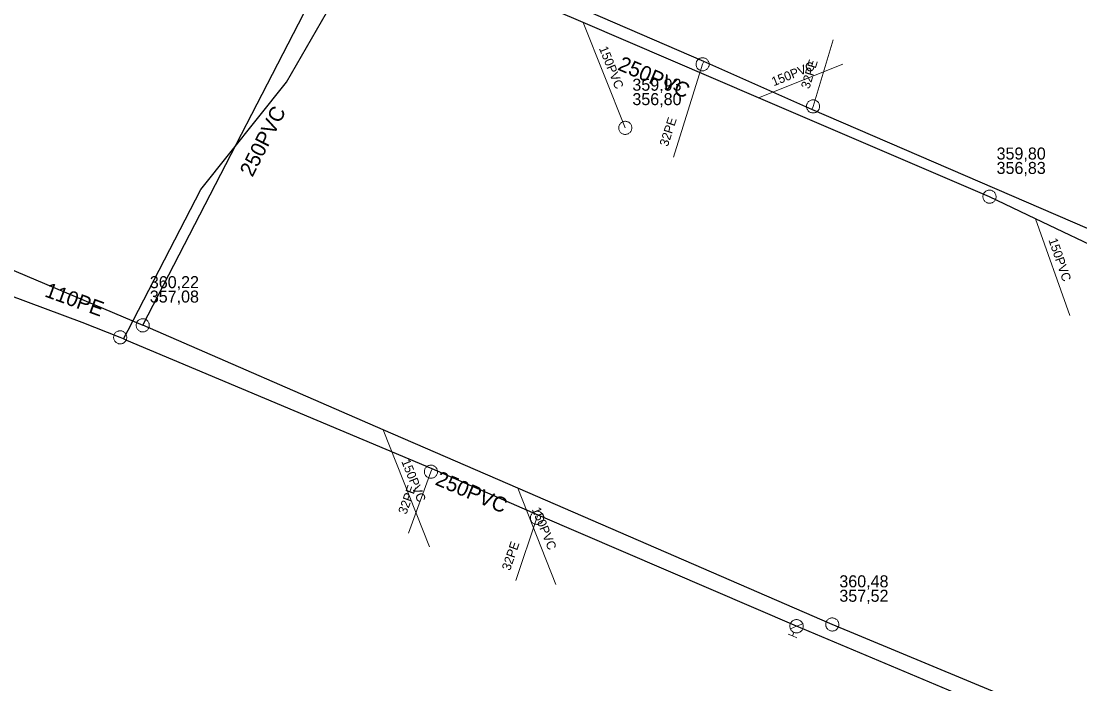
# Model space of a CAD drawing. Extents: x -741806 to -738704, y -1059275 to -1055387.
# Drawn here: x -740647.7 to -740577.2, y -1058217.7 to -1058173.6 of the extents above; entities that cross this region are included whole.
import ezdxf

# ---------------------------------------------------------------- set-up
doc = ezdxf.new("R2010")
doc.units = 0
doc.header["$LTSCALE"] = 0.4
for name, color, linetype, lineweight in [('2', 7, 'Continuous', 25), ('21', 7, 'Continuous', 13), ('3', 7, 'Continuous', 13), ('50', 7, 'Continuous', 13), ('51', 7, 'Continuous', 13), ('52', 7, 'Continuous', 25), ('56', 7, 'Continuous', 13), ('6', 7, 'Continuous', 13)]:
    doc.layers.add(name, color=color, linetype=linetype, lineweight=lineweight)
for name, color, linetype in [('5', 7, 'Continuous'), ('53', 7, 'Continuous'), ('54', 7, 'Continuous'), ('55', 7, 'Continuous')]:
    doc.layers.add(name, color=color, linetype=linetype)

msp = doc.modelspace()

# ---------------------------------------------------------------- linework, layer by layer
at = {"layer": '2'}
for points in [[(-740583.26, -1058185.25), (-740598.636, -1058178.666), (-740610.313, -1058173.665), (-740625.809, -1058167.03), (-740606.009, -1058125.064), (-740592.5, -1058086.389)], [(-740593.73, -1058213.72), (-740614.653, -1058204.646), (-740623.623, -1058200.756), (-740639.64, -1058193.81), (-740625.809, -1058167.03)], [(-740660.07, -1058185.139), (-740658.399, -1058185.85), (-740639.64, -1058193.81)], [(-740538.76, -1058206.54), (-740547.691, -1058202.267), (-740571.346, -1058190.95), (-740575.151, -1058189.129), (-740580.188, -1058186.719), (-740583.26, -1058185.25)], [(-740548.32, -1058232.629), (-740563.6, -1058226.267), (-740576.074, -1058221.071), (-740593.73, -1058213.72)]]:
    msp.add_lwpolyline(points, dxfattribs=at)
at = {"layer": '21'}
for points in [[(-740595.099, -1058179.439), (-740595.009, -1058179.237), (-740593.67, -1058174.82)], [(-740602.27, -1058176.253), (-740602.363, -1058176.438), (-740604.289, -1058182.62)], [(-740620.362, -1058203.362), (-740620.449, -1058203.55), (-740621.94, -1058207.639)], [(-740613.302, -1058206.436), (-740613.39, -1058206.62), (-740614.8, -1058210.79)]]:
    msp.add_lwpolyline(points, dxfattribs=at)
at = {"layer": '3'}
for points in [[(-740607.672, -1058180.262), (-740607.712, -1058180.281), (-740607.752, -1058180.304), (-740607.789, -1058180.332), (-740607.822, -1058180.363), (-740607.852, -1058180.397), (-740607.879, -1058180.435), (-740607.901, -1058180.475), (-740607.92, -1058180.517), (-740607.932, -1058180.561), (-740607.941, -1058180.605), (-740607.946, -1058180.651), (-740607.945, -1058180.698), (-740607.939, -1058180.743), (-740607.93, -1058180.787), (-740607.915, -1058180.831), (-740607.896, -1058180.873), (-740607.872, -1058180.911), (-740607.845, -1058180.948), (-740607.813, -1058180.982), (-740607.779, -1058181.012), (-740607.741, -1058181.038), (-740607.702, -1058181.06), (-740607.659, -1058181.079), (-740607.616, -1058181.092), (-740607.571, -1058181.101), (-740607.525, -1058181.105), (-740607.48, -1058181.105), (-740607.434, -1058181.099), (-740607.389, -1058181.089), (-740607.346, -1058181.074), (-740607.305, -1058181.055), (-740607.265, -1058181.032), (-740607.228, -1058181.004), (-740607.195, -1058180.972), (-740607.165, -1058180.939), (-740607.138, -1058180.901), (-740607.116, -1058180.861), (-740607.098, -1058180.818), (-740607.085, -1058180.775), (-740607.076, -1058180.731), (-740607.072, -1058180.685), (-740607.072, -1058180.639), (-740607.077, -1058180.593), (-740607.087, -1058180.549), (-740607.102, -1058180.506), (-740607.121, -1058180.464), (-740607.145, -1058180.424), (-740607.172, -1058180.388), (-740607.204, -1058180.354), (-740607.239, -1058180.324), (-740607.276, -1058180.298), (-740607.315, -1058180.275), (-740607.358, -1058180.258), (-740607.401, -1058180.244), (-740607.447, -1058180.235), (-740607.492, -1058180.231), (-740607.537, -1058180.232), (-740607.584, -1058180.237), (-740607.628, -1058180.247), (-740607.671, -1058180.261)], [(-740583.654, -1058185.06), (-740583.671, -1058185.102), (-740583.684, -1058185.146), (-740583.693, -1058185.191), (-740583.697, -1058185.236), (-740583.695, -1058185.282), (-740583.69, -1058185.328), (-740583.678, -1058185.372), (-740583.664, -1058185.416), (-740583.643, -1058185.457), (-740583.62, -1058185.496), (-740583.592, -1058185.532), (-740583.561, -1058185.566), (-740583.526, -1058185.595), (-740583.488, -1058185.622), (-740583.448, -1058185.643), (-740583.405, -1058185.661), (-740583.361, -1058185.674), (-740583.317, -1058185.683), (-740583.271, -1058185.686), (-740583.225, -1058185.685), (-740583.18, -1058185.678), (-740583.136, -1058185.668), (-740583.092, -1058185.653), (-740583.051, -1058185.634), (-740583.011, -1058185.609), (-740582.976, -1058185.581), (-740582.942, -1058185.55), (-740582.912, -1058185.515), (-740582.886, -1058185.477), (-740582.865, -1058185.437), (-740582.847, -1058185.395), (-740582.834, -1058185.352), (-740582.825, -1058185.306), (-740582.822, -1058185.26), (-740582.823, -1058185.215), (-740582.829, -1058185.169), (-740582.84, -1058185.125), (-740582.855, -1058185.081), (-740582.875, -1058185.041), (-740582.898, -1058185.002), (-740582.926, -1058184.965), (-740582.958, -1058184.931), (-740582.992, -1058184.901), (-740583.03, -1058184.876), (-740583.07, -1058184.854), (-740583.113, -1058184.836), (-740583.156, -1058184.823), (-740583.201, -1058184.815), (-740583.247, -1058184.811), (-740583.293, -1058184.813), (-740583.338, -1058184.819), (-740583.383, -1058184.829), (-740583.426, -1058184.844), (-740583.467, -1058184.864), (-740583.507, -1058184.888), (-740583.543, -1058184.916), (-740583.576, -1058184.947), (-740583.606, -1058184.982), (-740583.632, -1058185.02), (-740583.654, -1058185.059)], [(-740639.438, -1058193.421), (-740639.479, -1058193.403), (-740639.523, -1058193.388), (-740639.568, -1058193.378), (-740639.613, -1058193.373), (-740639.659, -1058193.373), (-740639.705, -1058193.377), (-740639.749, -1058193.387), (-740639.793, -1058193.4), (-740639.835, -1058193.419), (-740639.874, -1058193.442), (-740639.912, -1058193.468), (-740639.947, -1058193.499), (-740639.977, -1058193.533), (-740640.004, -1058193.569), (-740640.027, -1058193.609), (-740640.047, -1058193.651), (-740640.06, -1058193.695), (-740640.071, -1058193.739), (-740640.075, -1058193.785), (-740640.075, -1058193.831), (-740640.071, -1058193.876), (-740640.062, -1058193.92), (-740640.048, -1058193.965), (-740640.03, -1058194.006), (-740640.007, -1058194.046), (-740639.979, -1058194.083), (-740639.95, -1058194.117), (-740639.915, -1058194.149), (-740639.879, -1058194.176), (-740639.839, -1058194.198), (-740639.798, -1058194.217), (-740639.755, -1058194.232), (-740639.709, -1058194.242), (-740639.663, -1058194.246), (-740639.618, -1058194.247), (-740639.572, -1058194.243), (-740639.528, -1058194.233), (-740639.483, -1058194.219), (-740639.442, -1058194.201), (-740639.403, -1058194.178), (-740639.365, -1058194.151), (-740639.33, -1058194.121), (-740639.3, -1058194.087), (-740639.273, -1058194.051), (-740639.25, -1058194.011), (-740639.231, -1058193.969), (-740639.216, -1058193.926), (-740639.207, -1058193.881), (-740639.202, -1058193.835), (-740639.202, -1058193.789), (-740639.207, -1058193.744), (-740639.215, -1058193.699), (-740639.23, -1058193.655), (-740639.247, -1058193.614), (-740639.271, -1058193.573), (-740639.297, -1058193.536), (-740639.327, -1058193.503), (-740639.362, -1058193.471), (-740639.399, -1058193.444), (-740639.437, -1058193.421)], [(-740594.134, -1058213.551), (-740594.148, -1058213.593), (-740594.159, -1058213.638), (-740594.165, -1058213.684), (-740594.167, -1058213.729), (-740594.163, -1058213.775), (-740594.155, -1058213.82), (-740594.142, -1058213.864), (-740594.125, -1058213.906), (-740594.102, -1058213.946), (-740594.077, -1058213.984), (-740594.047, -1058214.019), (-740594.014, -1058214.051), (-740593.977, -1058214.078), (-740593.939, -1058214.103), (-740593.897, -1058214.122), (-740593.854, -1058214.138), (-740593.809, -1058214.148), (-740593.765, -1058214.155), (-740593.718, -1058214.156), (-740593.672, -1058214.152), (-740593.628, -1058214.144), (-740593.585, -1058214.131), (-740593.542, -1058214.114), (-740593.501, -1058214.092), (-740593.463, -1058214.066), (-740593.429, -1058214.036), (-740593.397, -1058214.004), (-740593.369, -1058213.967), (-740593.345, -1058213.928), (-740593.326, -1058213.886), (-740593.31, -1058213.844), (-740593.299, -1058213.8), (-740593.293, -1058213.753), (-740593.292, -1058213.707), (-740593.295, -1058213.663), (-740593.303, -1058213.617), (-740593.317, -1058213.573), (-740593.334, -1058213.53), (-740593.356, -1058213.491), (-740593.381, -1058213.453), (-740593.411, -1058213.418), (-740593.444, -1058213.386), (-740593.48, -1058213.358), (-740593.519, -1058213.334), (-740593.561, -1058213.315), (-740593.604, -1058213.299), (-740593.648, -1058213.288), (-740593.694, -1058213.282), (-740593.74, -1058213.281), (-740593.786, -1058213.285), (-740593.83, -1058213.293), (-740593.874, -1058213.305), (-740593.917, -1058213.324), (-740593.957, -1058213.345), (-740593.995, -1058213.371), (-740594.03, -1058213.401), (-740594.061, -1058213.434), (-740594.089, -1058213.471), (-740594.113, -1058213.509), (-740594.133, -1058213.55)]]:
    msp.add_lwpolyline(points, dxfattribs=at)
at = {"layer": '50'}
for p, q in [((-740596.107, -1058213.835), (-740596.518, -1058214.001)), ((-740596.279, -1058214.248), (-740596.376, -1058214.479)), ((-740596.107, -1058213.835), (-740595.692, -1058213.666)), ((-740596.659, -1058214.36), (-740596.376, -1058214.479)), ((-740596.092, -1058214.599), (-740596.376, -1058214.479))]:
    msp.add_line(p, q, dxfattribs=at)
msp.add_lwpolyline([(-740596.515, -1058213.66), (-740596.531, -1058213.706), (-740596.544, -1058213.75), (-740596.55, -1058213.798), (-740596.551, -1058213.844), (-740596.549, -1058213.888), (-740596.54, -1058213.937), (-740596.527, -1058213.98), (-740596.51, -1058214.025), (-740596.489, -1058214.066), (-740596.461, -1058214.104), (-740596.432, -1058214.14), (-740596.4, -1058214.174), (-740596.361, -1058214.201), (-740596.322, -1058214.226), (-740596.281, -1058214.247), (-740596.237, -1058214.262), (-740596.194, -1058214.275), (-740596.146, -1058214.281), (-740596.099, -1058214.282), (-740596.051, -1058214.279), (-740596.007, -1058214.271), (-740595.961, -1058214.259), (-740595.918, -1058214.241), (-740595.878, -1058214.22), (-740595.838, -1058214.194), (-740595.801, -1058214.164), (-740595.77, -1058214.131), (-740595.739, -1058214.094), (-740595.717, -1058214.053), (-740595.693, -1058214.013), (-740595.678, -1058213.968), (-740595.667, -1058213.922), (-740595.661, -1058213.879), (-740595.658, -1058213.83), (-740595.662, -1058213.784), (-740595.669, -1058213.737), (-740595.683, -1058213.694), (-740595.699, -1058213.649), (-740595.722, -1058213.607), (-740595.748, -1058213.57), (-740595.779, -1058213.533), (-740595.812, -1058213.501), (-740595.847, -1058213.472), (-740595.889, -1058213.445), (-740595.93, -1058213.425), (-740595.973, -1058213.41), (-740596.019, -1058213.399), (-740596.066, -1058213.392), (-740596.111, -1058213.39), (-740596.16, -1058213.393), (-740596.204, -1058213.401), (-740596.251, -1058213.414), (-740596.293, -1058213.431), (-740596.334, -1058213.451), (-740596.372, -1058213.48), (-740596.409, -1058213.508), (-740596.442, -1058213.541), (-740596.469, -1058213.579), (-740596.494, -1058213.618)], close=True, dxfattribs=at)
at = {"layer": '51'}
for points in [[(-740601.926, -1058176.438), (-740601.928, -1058176.393), (-740601.935, -1058176.348), (-740601.947, -1058176.303), (-740601.963, -1058176.261), (-740601.984, -1058176.22), (-740602.009, -1058176.181), (-740602.038, -1058176.146), (-740602.07, -1058176.113), (-740602.106, -1058176.085), (-740602.144, -1058176.06), (-740602.185, -1058176.039), (-740602.228, -1058176.022), (-740602.272, -1058176.01), (-740602.317, -1058176.003), (-740602.363, -1058176.001), (-740602.409, -1058176.003), (-740602.454, -1058176.01), (-740602.498, -1058176.022), (-740602.541, -1058176.039), (-740602.582, -1058176.06), (-740602.62, -1058176.085), (-740602.656, -1058176.113), (-740602.688, -1058176.146), (-740602.717, -1058176.181), (-740602.742, -1058176.22), (-740602.763, -1058176.261), (-740602.779, -1058176.303), (-740602.791, -1058176.348), (-740602.798, -1058176.393), (-740602.801, -1058176.439), (-740602.798, -1058176.484), (-740602.791, -1058176.529), (-740602.779, -1058176.574), (-740602.763, -1058176.616), (-740602.742, -1058176.657), (-740602.717, -1058176.696), (-740602.688, -1058176.731), (-740602.656, -1058176.764), (-740602.62, -1058176.792), (-740602.582, -1058176.817), (-740602.541, -1058176.838), (-740602.498, -1058176.855), (-740602.454, -1058176.866), (-740602.409, -1058176.874), (-740602.363, -1058176.876), (-740602.317, -1058176.874), (-740602.272, -1058176.866), (-740602.228, -1058176.855), (-740602.185, -1058176.838), (-740602.144, -1058176.817), (-740602.106, -1058176.792), (-740602.07, -1058176.764), (-740602.038, -1058176.731), (-740602.009, -1058176.696), (-740601.984, -1058176.657), (-740601.963, -1058176.616), (-740601.947, -1058176.574), (-740601.935, -1058176.529), (-740601.928, -1058176.484), (-740601.926, -1058176.439)], [(-740594.571, -1058179.237), (-740594.573, -1058179.192), (-740594.581, -1058179.147), (-740594.593, -1058179.102), (-740594.608, -1058179.06), (-740594.63, -1058179.019), (-740594.654, -1058178.98), (-740594.684, -1058178.945), (-740594.716, -1058178.912), (-740594.752, -1058178.884), (-740594.789, -1058178.859), (-740594.831, -1058178.838), (-740594.874, -1058178.821), (-740594.918, -1058178.809), (-740594.963, -1058178.802), (-740595.009, -1058178.8), (-740595.054, -1058178.802), (-740595.1, -1058178.809), (-740595.144, -1058178.821), (-740595.186, -1058178.838), (-740595.228, -1058178.859), (-740595.266, -1058178.884), (-740595.301, -1058178.912), (-740595.333, -1058178.945), (-740595.363, -1058178.98), (-740595.387, -1058179.019), (-740595.409, -1058179.06), (-740595.424, -1058179.102), (-740595.436, -1058179.147), (-740595.444, -1058179.192), (-740595.446, -1058179.238), (-740595.444, -1058179.283), (-740595.436, -1058179.328), (-740595.424, -1058179.373), (-740595.409, -1058179.415), (-740595.387, -1058179.456), (-740595.363, -1058179.495), (-740595.333, -1058179.53), (-740595.301, -1058179.563), (-740595.266, -1058179.591), (-740595.228, -1058179.616), (-740595.186, -1058179.637), (-740595.144, -1058179.654), (-740595.1, -1058179.665), (-740595.054, -1058179.673), (-740595.009, -1058179.675), (-740594.963, -1058179.673), (-740594.918, -1058179.665), (-740594.874, -1058179.654), (-740594.831, -1058179.637), (-740594.789, -1058179.616), (-740594.752, -1058179.591), (-740594.716, -1058179.563), (-740594.684, -1058179.53), (-740594.654, -1058179.495), (-740594.63, -1058179.456), (-740594.608, -1058179.415), (-740594.593, -1058179.373), (-740594.581, -1058179.328), (-740594.573, -1058179.283), (-740594.571, -1058179.238)], [(-740641.534, -1058194.421), (-740641.551, -1058194.462), (-740641.564, -1058194.506), (-740641.573, -1058194.552), (-740641.577, -1058194.596), (-740641.575, -1058194.642), (-740641.569, -1058194.688), (-740641.558, -1058194.732), (-740641.544, -1058194.776), (-740641.523, -1058194.817), (-740641.5, -1058194.856), (-740641.472, -1058194.892), (-740641.44, -1058194.926), (-740641.406, -1058194.956), (-740641.368, -1058194.982), (-740641.328, -1058195.003), (-740641.285, -1058195.021), (-740641.242, -1058195.034), (-740641.197, -1058195.043), (-740641.151, -1058195.046), (-740641.105, -1058195.045), (-740641.06, -1058195.038), (-740641.015, -1058195.029), (-740640.972, -1058195.013), (-740640.931, -1058194.994), (-740640.891, -1058194.969), (-740640.855, -1058194.941), (-740640.822, -1058194.91), (-740640.792, -1058194.875), (-740640.766, -1058194.837), (-740640.744, -1058194.797), (-740640.727, -1058194.755), (-740640.714, -1058194.711), (-740640.705, -1058194.666), (-740640.702, -1058194.621), (-740640.703, -1058194.575), (-740640.709, -1058194.529), (-740640.72, -1058194.485), (-740640.734, -1058194.441), (-740640.755, -1058194.4), (-740640.778, -1058194.361), (-740640.806, -1058194.325), (-740640.838, -1058194.291), (-740640.873, -1058194.262), (-740640.91, -1058194.235), (-740640.95, -1058194.214), (-740640.993, -1058194.196), (-740641.037, -1058194.184), (-740641.081, -1058194.175), (-740641.127, -1058194.171), (-740641.174, -1058194.173), (-740641.219, -1058194.179), (-740641.263, -1058194.189), (-740641.306, -1058194.205), (-740641.348, -1058194.224), (-740641.387, -1058194.248), (-740641.423, -1058194.276), (-740641.456, -1058194.307), (-740641.486, -1058194.342), (-740641.512, -1058194.38), (-740641.533, -1058194.42)], [(-740620.634, -1058203.945), (-740620.593, -1058203.962), (-740620.549, -1058203.975), (-740620.503, -1058203.983), (-740620.458, -1058203.987), (-740620.412, -1058203.985), (-740620.366, -1058203.979), (-740620.322, -1058203.967), (-740620.279, -1058203.952), (-740620.238, -1058203.932), (-740620.199, -1058203.908), (-740620.163, -1058203.88), (-740620.129, -1058203.848), (-740620.1, -1058203.813), (-740620.074, -1058203.775), (-740620.053, -1058203.735), (-740620.035, -1058203.692), (-740620.023, -1058203.648), (-740620.015, -1058203.603), (-740620.012, -1058203.557), (-740620.014, -1058203.511), (-740620.02, -1058203.466), (-740620.03, -1058203.422), (-740620.047, -1058203.379), (-740620.066, -1058203.338), (-740620.091, -1058203.298), (-740620.119, -1058203.262), (-740620.15, -1058203.23), (-740620.186, -1058203.2), (-740620.224, -1058203.174), (-740620.264, -1058203.152), (-740620.306, -1058203.136), (-740620.35, -1058203.123), (-740620.396, -1058203.115), (-740620.441, -1058203.112), (-740620.487, -1058203.113), (-740620.533, -1058203.119), (-740620.577, -1058203.131), (-740620.62, -1058203.146), (-740620.661, -1058203.166), (-740620.699, -1058203.19), (-740620.736, -1058203.218), (-740620.769, -1058203.25), (-740620.798, -1058203.285), (-740620.824, -1058203.323), (-740620.846, -1058203.364), (-740620.863, -1058203.406), (-740620.875, -1058203.45), (-740620.884, -1058203.495), (-740620.887, -1058203.541), (-740620.885, -1058203.587), (-740620.879, -1058203.632), (-740620.868, -1058203.676), (-740620.852, -1058203.719), (-740620.833, -1058203.761), (-740620.808, -1058203.8), (-740620.78, -1058203.836), (-740620.748, -1058203.868), (-740620.713, -1058203.898), (-740620.675, -1058203.924), (-740620.635, -1058203.945)], [(-740613.577, -1058207.014), (-740613.535, -1058207.032), (-740613.492, -1058207.045), (-740613.446, -1058207.053), (-740613.401, -1058207.057), (-740613.355, -1058207.055), (-740613.309, -1058207.049), (-740613.265, -1058207.038), (-740613.221, -1058207.023), (-740613.181, -1058207.003), (-740613.142, -1058206.979), (-740613.105, -1058206.951), (-740613.072, -1058206.919), (-740613.042, -1058206.885), (-740613.016, -1058206.847), (-740612.995, -1058206.806), (-740612.977, -1058206.764), (-740612.964, -1058206.72), (-740612.956, -1058206.675), (-740612.953, -1058206.629), (-740612.955, -1058206.583), (-740612.961, -1058206.538), (-740612.971, -1058206.493), (-740612.987, -1058206.45), (-740613.006, -1058206.409), (-740613.031, -1058206.37), (-740613.059, -1058206.333), (-740613.09, -1058206.301), (-740613.126, -1058206.271), (-740613.163, -1058206.245), (-740613.204, -1058206.223), (-740613.246, -1058206.206), (-740613.289, -1058206.193), (-740613.335, -1058206.185), (-740613.38, -1058206.182), (-740613.426, -1058206.183), (-740613.472, -1058206.189), (-740613.516, -1058206.2), (-740613.559, -1058206.215), (-740613.6, -1058206.236), (-740613.639, -1058206.259), (-740613.675, -1058206.287), (-740613.709, -1058206.319), (-740613.738, -1058206.354), (-740613.764, -1058206.391), (-740613.786, -1058206.432), (-740613.804, -1058206.475), (-740613.816, -1058206.519), (-740613.825, -1058206.563), (-740613.828, -1058206.609), (-740613.826, -1058206.655), (-740613.82, -1058206.7), (-740613.81, -1058206.745), (-740613.794, -1058206.788), (-740613.775, -1058206.829), (-740613.75, -1058206.868), (-740613.722, -1058206.905), (-740613.691, -1058206.937), (-740613.655, -1058206.967), (-740613.617, -1058206.993), (-740613.578, -1058207.014)]]:
    msp.add_lwpolyline(points, dxfattribs=at)
at = {"layer": '52'}
for points in [[(-740640.916, -1058194.717), (-740640.617, -1058194.136), (-740635.78, -1058184.78), (-740630.059, -1058177.62), (-740624.085, -1058167.223), (-740623.879, -1058166.87)], [(-740375.044, -1058278.037), (-740378.824, -1058273.34), (-740394.89, -1058265.49), (-740400.5, -1058262.541), (-740409.548, -1058258.602), (-740416.798, -1058255.547), (-740435.443, -1058248.414), (-740442.241, -1058245.764), (-740464.396, -1058237.183), (-740473.081, -1058233.814), (-740479.142, -1058231.466), (-740486.337, -1058228.676), (-740513.46, -1058216.94), (-740523.39, -1058212.448), (-740529.642, -1058209.397), (-740536.912, -1058206.021), (-740544.259, -1058202.333), (-740565.754, -1058192.476), (-740572.673, -1058189.165), (-740573.656, -1058188.705), (-740595.099, -1058179.439), (-740602.27, -1058176.253), (-740623.44, -1058167.1), (-740623.879, -1058166.87)], [(-740640.916, -1058194.717), (-740641.14, -1058194.61), (-740643.67, -1058193.629), (-740660.78, -1058187.26), (-740679.48, -1058180.33), (-740695.26, -1058174.48), (-740695.73, -1058174.379)], [(-740374.838, -1058278.283), (-740388.708, -1058289.415), (-740397.513, -1058296.936), (-740399.568, -1058297), (-740414.59, -1058291.034), (-740423.02, -1058287.375), (-740430.25, -1058284.409), (-740451.511, -1058275.193), (-740469.697, -1058267.465), (-740515.644, -1058247.906), (-740523.182, -1058244.761), (-740564.783, -1058227.061), (-740572.07, -1058223.941), (-740596.109, -1058213.84), (-740613.302, -1058206.436), (-740620.362, -1058203.362), (-740640.699, -1058194.82), (-740640.916, -1058194.717)]]:
    msp.add_lwpolyline(points, dxfattribs=at)
at = {"layer": '56'}
for p, q in [((-740607.51, -1058180.669), (-740610.313, -1058173.665)), ((-740593.028, -1058176.419), (-740598.636, -1058178.666)), ((-740577.921, -1058193.149), (-740580.188, -1058186.719)), ((-740620.539, -1058208.56), (-740623.623, -1058200.756)), ((-740612.124, -1058211.051), (-740614.653, -1058204.646))]:
    msp.add_line(p, q, dxfattribs=at)

# ---------------------------------------------------------------- texts
at = {"layer": '5'}
for rotation, p in [(337, (-740608.073, -1058176.783)), (63, (-740632.337, -1058183.995)), (337, (-740620.227, -1058204.392))]:
    msp.add_text('250PVC', height=1, rotation=rotation, dxfattribs=at).set_placement(p)
at = {"layer": '53'}
msp.add_text('110PE ', height=1, rotation=340, dxfattribs=at).set_placement((-740646.23, -1058191.873))
at = {"layer": '54'}
for rotation, p in [(73, (-740595.256, -1058178.115)), (72, (-740604.679, -1058181.953)), (70, (-740622.089, -1058206.432)), (71, (-740615.184, -1058210.175))]:
    msp.add_text('32PE', height=0.6, rotation=rotation, dxfattribs=at).set_placement(p)
at = {"layer": '55'}
for rotation, p in [(292, (-740609.273, -1058175.373)), (22, (-740597.625, -1058177.904)), (289, (-740579.341, -1058188.126)), (292, (-740622.435, -1058202.862)), (292, (-740613.742, -1058206.052))]:
    msp.add_text('150PVC', height=0.6, rotation=rotation, dxfattribs=at).set_placement(p)
at = {"layer": '6'}
for s, p in [('359,93', (-740607.037, -1058178.196)), ('356,80', (-740607.037, -1058179.156)), ('359,80', (-740582.787, -1058182.776)), ('356,83', (-740582.787, -1058183.736)), ('360,22', (-740639.167, -1058191.336)), ('357,08', (-740639.167, -1058192.296)), ('360,48', (-740593.257, -1058211.246)), ('357,52', (-740593.257, -1058212.206))]:
    msp.add_text(s, height=0.8, dxfattribs=at).set_placement(p)

doc.saveas('drawing.dxf')
